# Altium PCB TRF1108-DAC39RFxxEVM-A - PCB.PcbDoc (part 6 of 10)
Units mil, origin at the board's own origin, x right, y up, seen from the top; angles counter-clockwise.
Board outline 4951.22 x 2726.56 mil, 16 copper layers (Top Layer, L2 GND1, L3 PWR1, L4 GND2, L5 PWR2, L6 GND3, L7 Ctrl Signal 1, L8 GND4, L9 GND5, L10 Ctrl Signal 2, L11 GND6, L12 PWR3, L13 GND7, L14 PWR4, L15 GND8, Bottom Layer), stack 80.2 mil thick; 705 components, 433 nets, 3633 pads, 1678 vias.
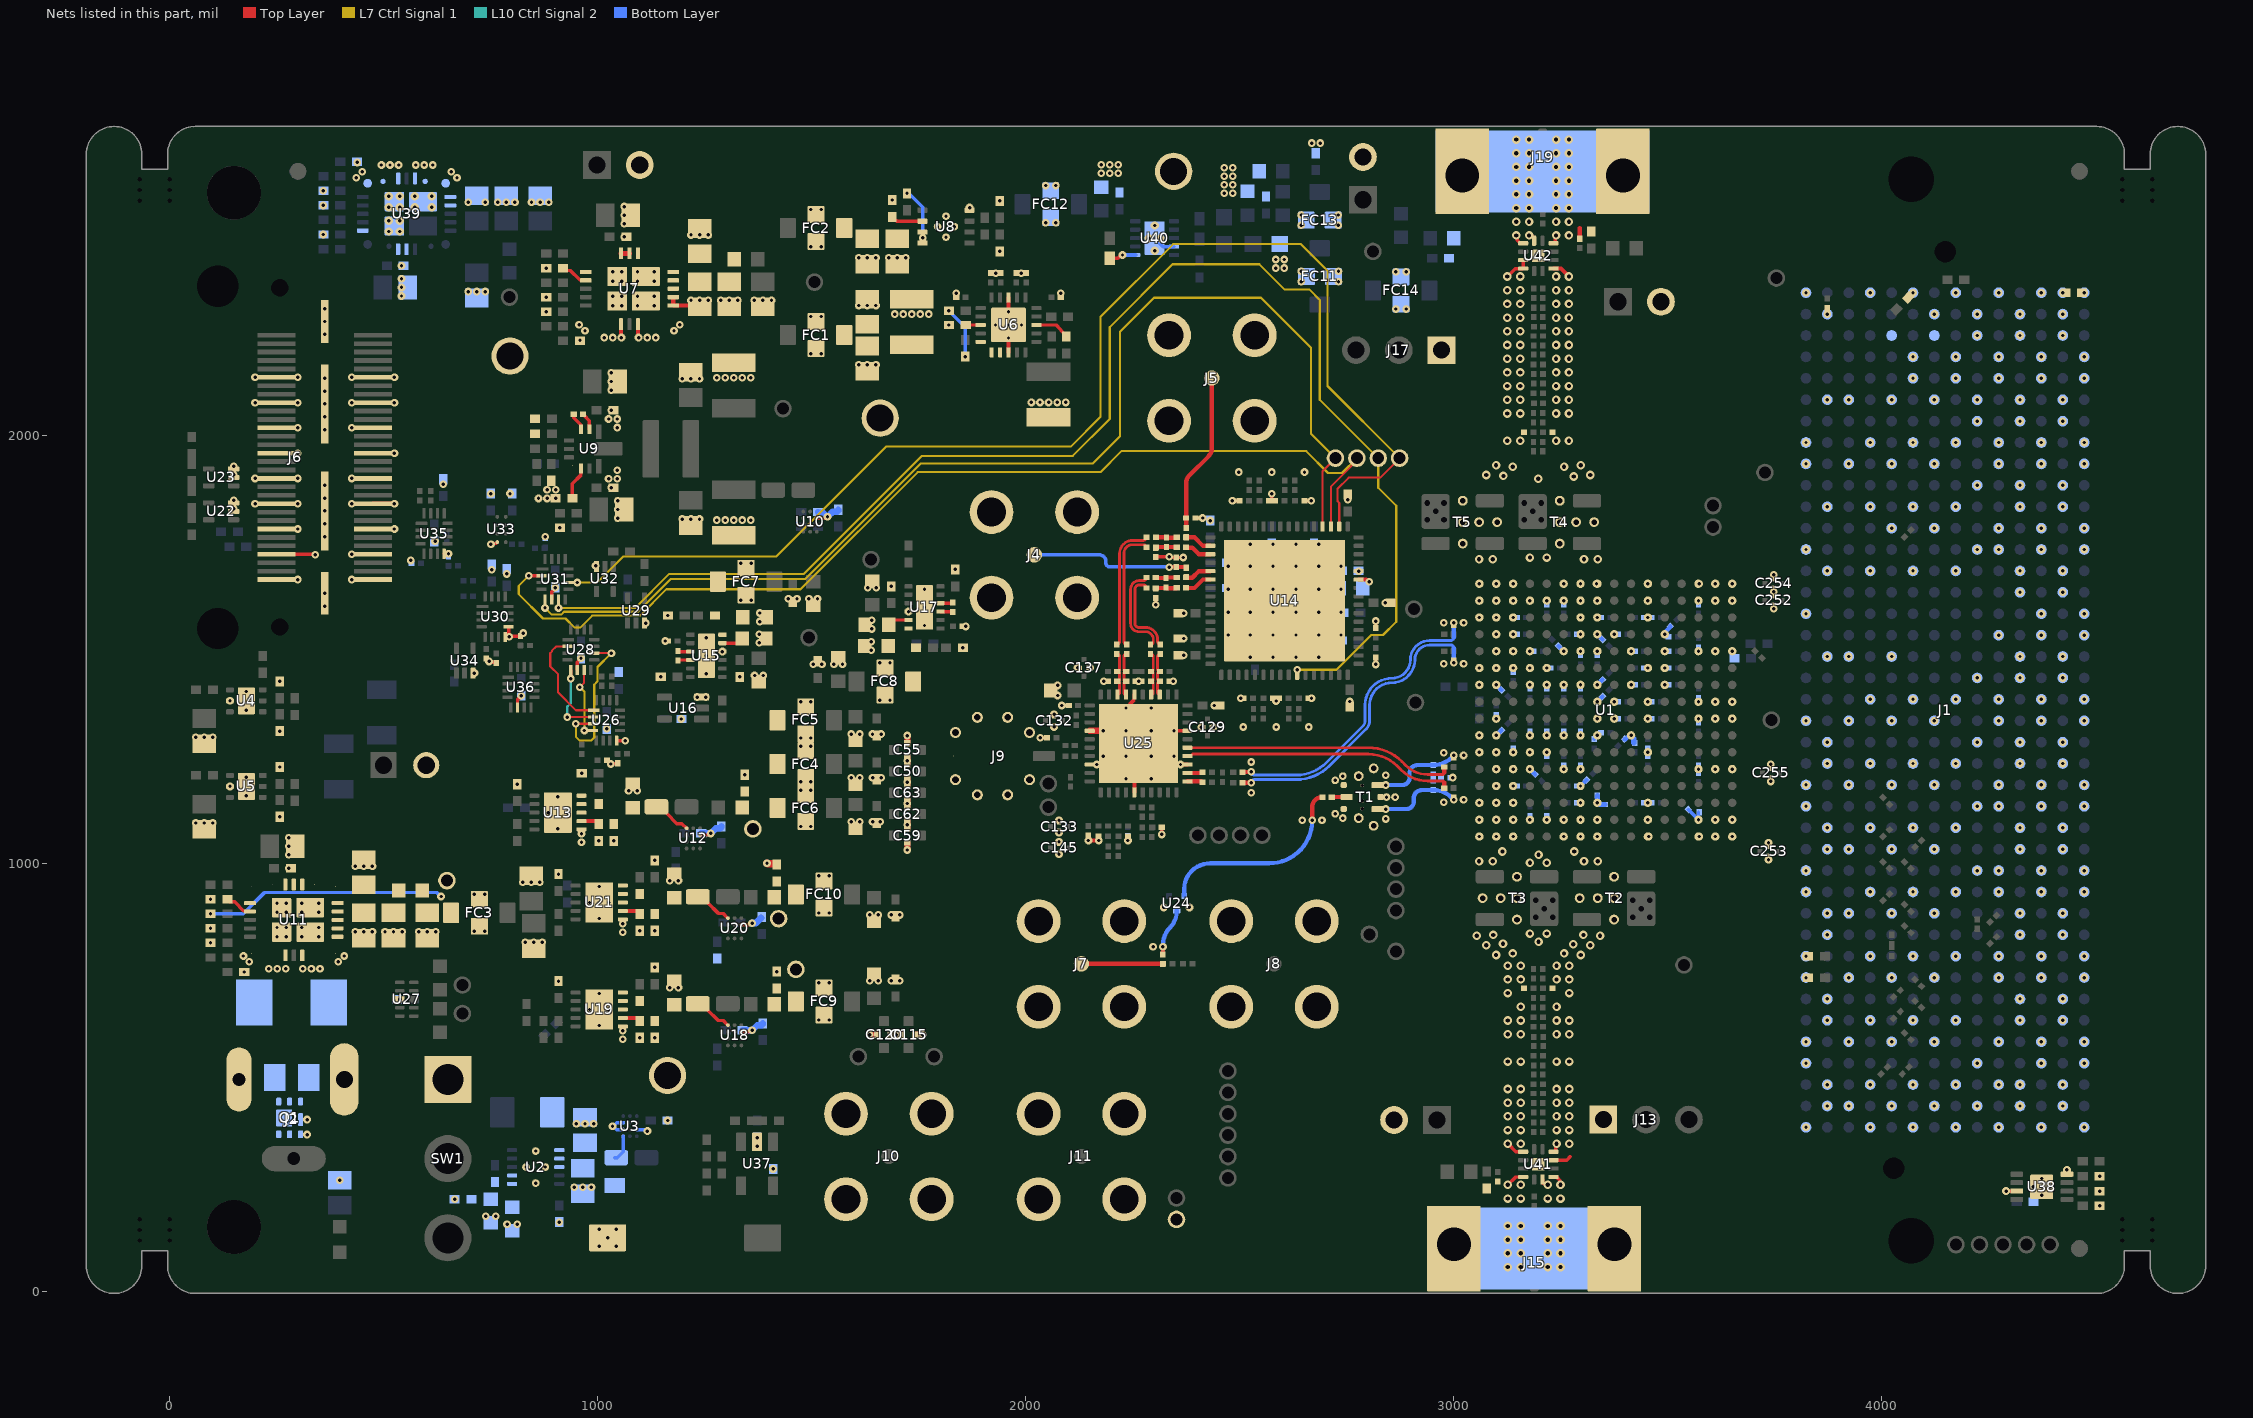
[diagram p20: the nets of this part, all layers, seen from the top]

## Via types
v1: diameter 18, hole 8, Top Layer to Bottom Layer, tented both sides, 1468 vias
v2: diameter 20, hole 10.01, Top Layer to Bottom Layer, 187 vias
v3: diameter 19.68, hole 7.87, Top Layer to Bottom Layer, tented both sides, 16 vias
v4: diameter 19.68, hole 7.87, Top Layer to Bottom Layer, 6 vias
v5: diameter 18/18/18/18/18/18/18/18/18/18/18/18/18/18/18/18 (per signal layer), hole 8, Top Layer to Bottom Layer, tented both sides, 1 vias

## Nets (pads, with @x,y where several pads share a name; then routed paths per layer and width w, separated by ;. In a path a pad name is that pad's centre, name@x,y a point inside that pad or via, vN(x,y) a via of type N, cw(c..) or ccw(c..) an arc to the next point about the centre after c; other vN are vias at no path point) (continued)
GND: C2.1 C3.1 C4.2 C5.1 C6.1 C7.1 C8.1 C9.1 C10.1 C11.1 C12.1 C13.1 C15.1 C16.1 C17.1 C18.1 C19.1 C20.1 C21.1 C22.1 C23.1 C24.1 C25.1 C26.1 C27.1 C28.1 C29.1 C30.1 C31.1 C33.1 C34.1 C35.1 C36.1 C37.2 C38.1 C39.1 C40.1 C41.1 C42.1 C43.1 C44.1 C45.1 C46.1 C47.1 C48.2 C49.1 C50.2 C51.1 C52.1 C53.1 C54.1 C55.2 C56.1 C57.1 C58.1 C59.2 C60.1 C61.1 C62.2 C63.2 C67.1 C68.1 C69.1 C70.1 C71.1 C72.1 C77.1 C78.1 C79.1 C80.1 C81.1 C82.1 C94.1 C95.1 C96.2 C97.1 C98.1 C100.1 C101.1 C102.1 C103.1 C104.1 C105.1 C106.1 C108.1 C109.1 C110.1 C111.1 C112.1 C113.2 C114.1 C115.2 C116.1 C117.1 C118.1 C119.1 C120.2 C121.1 C122.2 C123.1 C124.1 C125.1 C126.1 C127.1 C128.1 C129.2 C130.2 C132.2 C133.2 C137.2 C145.2 C146.1 C147.1 C148.2 C154.1 C158.1 C159.2 C160.1 C161.2 C162.2 C163.2 C164.1 C165.2 C166.2 C167.2 C168.2 C169.2 C170.1 C171.1 C172.1 C173.2 C174.1 C175.1 C176.1 C177.1 C178.1 C179.1 C180.1 C181.2 C182.2 C184.2 C185.2 C186.2 C187.2 C188.1 C189.2 C190.1 C191.1 C192.1 C193.1 C194.1 C195.1 C196.1 C197.1 C198.1 C199.1 C200.1 C201.1 C202.1 C203.1 C204.1 C205.1 C206.1 C207.1 C208.1 C209.1 C210.1 C211.1 C212.1 C213.2 C214.2 C215.2 C216.2 C217.2 C218.2 C219.1 C220.1 C221.1 C222.1 C223.1 C224.1 C225.1 C226.1 C227.1 C228.1 C229.1 C230.1 C231.1 C232.1 C233.1 C234.1 C235.1 C236.2 C237.2 C238.2 C239.2 C240.2 C241.2 C242.1 C243.1 C244.1 C245.1 C246.1 C247.1 C248.1 C249.1 C250.1 C251.1 C252.2 C253.2 C254.2 C255.2 C256.1 C257.1 C258.1 C259.1 C260.1 C261.1 C262.1 C263.2 C264.2 C274.2 C275.2 C276.2 D1.2 FC1.2 FC2.2 FC3.2 FC4.2 FC5.2 FC6.2 FC7.2 FC8.2 FC9.2 FC10.2 FC11.2 FC12.2 FC13.2 FC14.2 J1.A1 J1.A4 J1.A5 J1.A8 J1.A9 J1.A12 J1.A13 J1.A16 J1.A17 J1.A20 J1.A21 J1.A24 J1.A25 J1.A28 J1.A29 J1.A32 J1.A33 J1.A36 J1.A37 J1.A40 J1.B2 J1.B3 J1.B6 J1.B7 J1.B10 J1.B11 J1.B14 J1.B15 J1.B18 J1.B19 J1.B22 J1.B23 J1.B26 J1.B27 J1.B30 J1.B31 J1.B34 J1.B35 J1.B38 J1.B39 J1.C1 J1.C4 J1.C5 J1.C8 J1.C9 J1.C12 J1.C13 J1.C17 J1.C20 J1.C21 J1.C24 J1.C25 J1.C28 J1.C29 J1.C32 J1.C33 J1.C36 J1.C38 J1.C40 J1.D2 J1.D3 J1.D6 J1.D7 J1.D10 J1.D13 J1.D19 J1.D22 J1.D25 J1.D28 J1.D37 J1.D39 J1.E1 J1.E4 J1.E5 J1.E8 J1.E11 J1.E14 J1.E20 J1.E23 J1.E26 J1.E29 J1.E32 J1.E35 J1.E38 J1.E40 J1.F2 J1.F3 J1.F6 J1.F9 J1.F12 J1.F21 J1.F24 J1.F27 J1.F30 J1.F33 J1.F36 J1.F39 J1.G1 J1.G4 J1.G5 J1.G8 J1.G11 J1.G14 J1.G20 J1.G23 J1.G26 J1.G29 J1.G32 J1.G35 J1.G38 J1.G40 J1.H3 J1.H6 J1.H9 J1.H12 J1.H18 J1.H21 J1.H24 J1.H27 J1.H30 J1.H33 J1.H36 J1.H39 J1.J1 J1.J8 J1.J11 J1.J14 J1.J20 J1.J23 J1.J26 J1.J29 J1.J32 J1.J35 J1.J38 J1.J40 J1.K6 J1.K9 J1.K18 J1.K21 J1.K24 J1.K27 J1.K30 J1.K33 J1.K36 J1.K39 J1.L2 J1.L6 J1.L11 J1.L14 J1.L18 J1.L22 J1.L23 J1.L26 J1.L27 J1.L30 J1.L31 J1.L34 J1.L35 J1.L38 J1.L39 J1.M1 J1.M8 J1.M9 J1.M13 J1.M16 J1.M21 J1.M24 J1.M25 J1.M28 J1.M29 J1.M32 J1.M33 J1.M36 J1.M37 J1.M40 J1.Y1 J1.Y4 J1.Y5 J1.Y8 J1.Y9 J1.Y12 J1.Y13 J1.Y16 J1.Y17 J1.Y20 J1.Y21 J1.Y24 J1.Y25 J1.Y28 J1.Y29 J1.Y32 J1.Y33 J1.Y36 J1.Y37 J1.Y40 J1.Z2 J1.Z3 J1.Z6 J1.Z7 J1.Z10 J1.Z11 J1.Z14 J1.Z15 J1.Z18 J1.Z19 J1.Z22 J1.Z23 J1.Z26 J1.Z27 J1.Z30 J1.Z31 J1.Z34 J1.Z35 J1.Z38 J1.Z39 J3.2 J4.2 J4.3 J4.4 J4.5 J5.2 J5.3 J5.4 J5.5 J6.1 J6.2 J6.7 J6.8 J6.13 J6.14 J6.19 J6.20 J6.25 J6.26 J6.31 J6.32 J6.37 J6.38 J6.43 J6.44 J6.49 J6.50 J6.MP1 J6.MP2 J6.MP3 J6.MP4 J7.2 J7.3 J7.4 J7.5 J8.2 J8.3 J8.4 J8.5 J9.2 J10.2 J10.3 J10.4 J10.5 J11.2 J11.3 J11.4 J11.5 J12.2 J13.1 J14.2 J15.2 J15.3 J15.4 J16.2 J17.1 J18.2 J19.2 J19.3 J19.4 PP47.1 Q1.4 Q1.7 R3.1 R4.1 R5.1 R13.1 R14.1 R19.1 R21.1 R22.1 R23.1 R24.1 R26.1 R28.1 R29.1 R30.1 R33.1 R38.1 R39.1 R41.1 R42.1 R44.1 R47.1 R51.1 R52.1 R53.1 R55.1 R60.1 R61.1 R62.1 R66.1 R67.1 R71.1 R72.1 R73.1 R74.1 R75.1 R76.1 R77.1 R78.1 R79.1 R80.1 R81.1 R82.1 R83.1 R86.1 R87.1 R91.1 R92.1 R94.1 R99.1 R100.1 R101.1 R109.1 R110.1 R125.1 R126.1 R134.1 R137.1 R138.2 R139.2 R140.2 R141.2 R145.2 R147.1 R154.2 R155.2 R158.1 R162.1 R167.1 R169.1 R175.1 R180.1 R181.1 R182.1 R185.2 R192.2 R208.1 R213.1 R214.1 R215.1 R231.1 R232.1 R233.1 R234.1 R237.1 R242.2 R256.1 SW2.2 T1.1 T1.3 T1.5 T2.5 T3.5 T4.5 T5.5 TP1.1 TP2.1 TP3.1 U1.A1 U1.A2 U1.A3 U1.A6 U1.A9 U1.A10 U1.A11 U1.A14 U1.A15 U1.A16 U1.B1 U1.B2 U1.B3 U1.B6 U1.B9 U1.B10 U1.B11 U1.B12 U1.B13 U1.B14 U1.B15 U1.B16 U1.C6 U1.C9 U1.C10 U1.C14 U1.C15 U1.C16 U1.D10 U1.D14 U1.D15 U1.E1 U1.E2 U1.E3 U1.E10 U1.E11 U1.E13 U1.E14 U1.E15 U1.F6 U1.F12 U1.F13 U1.F14 U1.F15 U1.F16 U1.G7 U1.G9 U1.G10 U1.G11 U1.G12 U1.G13 U1.G15 U1.G16 U1.H1 U1.H2 U1.H3 U1.H6 U1.H8 U1.H9 U1.H15 U1.J1 U1.J2 U1.J3 U1.J6 U1.J8 U1.J9 U1.K5 U1.K7 U1.K9 U1.K10 U1.K11 U1.K12 U1.K13 U1.K15 U1.K16 U1.L5 U1.L6 U1.L12 U1.L13 U1.L14 U1.L15 U1.L16 U1.M1 U1.M2 U1.M3 U1.M5 U1.M7 U1.M9 U1.M10 U1.M11 U1.M13 U1.M14 U1.M15 U1.N5 U1.N8 U1.N9 U1.N10 U1.N14 U1.N15 U1.P6 U1.P9 U1.P10 U1.P14 U1.P15 U1.P16 U1.R1 U1.R2 U1.R3 U1.R6 U1.R9 U1.R10 U1.R11 U1.R12 U1.R13 U1.R14 U1.R15 U1.R16 U1.T1 U1.T2 U1.T3 U1.T6 U1.T9 U1.T10 U1.T11 U1.T14 U1.T15 U1.T16 U2.11 U3.B3 U3.C1 U3.C3 U4.5 U4.7@179.22,1357.95 U4.7@179.22,1379.61 U4.7@179.22,1401.26 U5.5 U5.7@179.22,1157.95 U5.7@179.22,1179.61 U5.7@179.22,1201.26 U6.8 U6.18 U6.21 U7.1 U7.2 U7.3 U7.5 U7.6 U7.7 U7.8 U7.9 U7.16 U7.17 U7.20 U7.25 U7.26 U7.28 U8.4 U8.9 U9.5 U9.9 U9.11 U10.C1 U11.1 U11.2 U11.3 U11.5 U11.6 U11.7 U11.8 U11.9 U11.16 U11.17 U11.20 U11.25 U11.26 U11.28 U12.C1 U13.6 U13.11 U14.65 U15.4 U15.13 U16.3 U17.4 U17.13 U18.C1 U19.6 U19.11 U20.C1 U21.6 U21.11 U22.2 U22.3 U23.2 U23.3 U24.GND U25.5 U25.13 U25.17 U25.26 U25.34 U25.38 U25.41 U26.8 U27.3@537.69,682.33 U28.6 U29.3 U30.8 U30.9 U31.6 U32.3 U33.D1 U34.3 U35.8 U36.6 U37.2 U38.4 U38.7 U38.9 U39.1 U39.2 U39.3 U39.5 U39.6 U39.7 U39.8 U39.9 U39.16 U39.17 U39.20 U39.25 U39.26 U39.28 U40.4 U40.6 U40.11@2301.04,2460.58 U41.1 U41.3 U41.4 U41.7 U41.10 U41.12 U41.13 U42.1 U42.3 U42.4 U42.7 U42.10 U42.12 U42.13 | length 4622.8
  Top Layer w8: v1(199.41,1840.04) J6.20@249.41,1840.04 v1(299.41,1840.04) ; v1(199.41,1899.09) J6.26@249.41,1899.09 v1(299.41,1899.09) ; v1(199.41,2076.26) J6.44@249.41,2076.26 v1(299.41,2076.26) ; v1(199.41,2135.31) J6.50@249.41,2135.31 v1(299.41,2135.31) ; J6.2@249.41,1662.87 v1(299.41,1662.87) ; J6.8@249.41,1721.93 339.1,1721.93 v1(339.85,1721.18) ; J6.14@249.41,1780.98 v1(299.41,1780.98) ; J6.32@249.41,1958.15 v1(299.41,1958.15) ; J6.38@249.41,2017.2 v1(299.41,2017.2) ; v1(425,1662.87) J6.1@475,1662.87 ; v1(425,1721.93) J6.7@475,1721.93 ; v1(425,1840.04) J6.19@475,1840.04 ; v1(425,1899.09) J6.25@475,1899.09 ; v1(425,2017.2) J6.37@475,2017.2 ; v1(425,2076.26) J6.43@475,2076.26 v1(525,2076.26) ; v1(425,2135.31) J6.49@475,2135.31 v1(525,2135.31) ; J6.13@475,1780.98 v1(525,1780.98) ; J6.31@475,1958.15 v1(525,1958.15) ; U35.8@641.32,1723.18 v1(651.32,1723.18) ; v1(746.12,1471.54) 748.04,1469.63 760.82,1469.63 R155.2@762.82,1467.63 ; v1(750.54,1745.15) 752.45,1747.07 762.17,1747.07 765.26,1750.15 U33.D1@765.54,1750.15 ; U30.9@791.94,1552.67 791.94,1530.11 v1(793,1529.05) 794.73,1530.77 R158.1@819.67,1530.77 ; U36.6@812.57,1364.05 812.57,1381.92 821,1390.35 v1(821,1391.61) ; U31.6@892.57,1616.55 892.57,1634.42 901,1642.85 v1(901,1644.11) ; U28.6@952.57,1451.55 952.57,1469.42 961,1477.85 v1(961,1479.11) ; R145.2@1021.21,1241.1 1022,1241.1 1030.34,1232.75 v1(1030.34,1232.05) 1031.16,1232.86 1045.6,1232.86 R147.1@1046.42,1233.68 ; U26.8@1044.07,1286.55 v1(1064.07,1286.55) ; U12.C1@1239.08,1066.1 1257.74,1066.1 1261.37,1069.73 v1(1264.08,1069.73) ; U18.C1@1335.57,606.1 v1@1354.24,606.1 ; U20.C1@1335.57,856.1 1354.24,856.1 1357.87,859.73 v1(1360.57,859.73) ; U10.C1@1511.85,1806.05 1530.52,1806.05 1534.14,1809.68 v1(1536.85,1809.68) ; R19.1@1837.66,2322.05 v1(1837.66,2332.05) ; R21.1@1918.3,2378.7 R22.1@1941.99,2378.7 ; R23.1@1977.36,2378.7 R24.1@2001.04,2378.7 ; v1(2034.02,1293.15) R126.1@2050.32,1293.15 ; R26.1@2081.68,2322.05 v1(2081.68,2332.05) ; v1(2084.07,1368.57) C148.2@2100.37,1368.57 ; U25.38@2149.41,1230.78 v1(2165.71,1230.78) 2214.37,1230.78 U25.41@2234.06,1250.46 2253.74,1230.78 U25.41@2253.74,1192.12 ; C188.1@2196.23,2413.33 2215.42,2413.33 2223.3,2421.21 v1(2225.93,2421.21) ; U25.41@2234.06,1362.67 2252.82,1381.43 2252.82,1393.24 U25.26@2253.74,1394.17 ; v1(2303.69,1603.99) R66.1@2303.69,1620.28 ; R71.1@2303.79,1715.13 2304.46,1715.8 2334.81,1715.8 v1(2335.48,1716.48) ; v1(2317.63,1067.47) R125.1@2317.63,1083.77 ; U25.41@2318.99,1291.1 U25.41@2330.51,1302.62 ; v1@2335.48,1714.48 R62.1@2351.78,1714.48 v1(2368.08,1714.48) ; U25.41@2346.26,1309.52 U25.17@2377.76,1309.52 ; R67.1@2396.78,1806.69 v1(2413.08,1806.69) ; v1(2482.76,1846.92) R81.1@2499.06,1846.92 ; v1(2502.05,1385.46) R74.1@2509.14,1385.46 ; 2575,1846.92 v1(2575,1863.22) ; R75.1@2577.76,1385.46 R76.1@2584.85,1385.46 ; v1(2584.85,1379.17) R76.1@2584.85,1385.46 ; R76.1@2591.93,1385.46 R76.1@2584.85,1385.46 ; R78.1@2650.94,1846.92 v1(2667.24,1846.92) ; R77.1@2660.55,1385.46 v1(2667.64,1385.46) ; v1(2817.76,1464.58) R72.1@2817.76,1480.88 ; R73.1@2817.76,1549.66 v1(2817.76,1565.96) ; v2@3126,248 3126,248.54 v2(3126.18,248.72) 3144.49,267.03 U41.10@3162.17,267.03 ; v2@3127,343 3127.91,343 3144.82,326.09 U41.7@3162.17,326.09 ; v2@3128,249 v2@3130.02,251.02 ; v2@3128,2374 3128.33,2374 3143.82,2389.49 U42.4@3160,2389.49 ; v2@3147,2464 3148.16,2462.84 3148.16,2455.66 3155.28,2448.54 U42.1@3162.17,2448.54 ; U42.4@3160,2389 3160.76,2389 3162.17,2390.41 U42.3@3162.17,2409.17 ; v2@3178,2469 3178,2467.97 3181.41,2464.56 3184.54,2464.56 3187.76,2461.34 U42.12@3187.76,2454.45 ; U41.12@3207.44,261.13 3207.44,254.24 3210.66,251.02 3216.98,251.02 v2@3219,249 ; U41.1@3233.03,267.03 3239.92,267.03 3247.04,259.92 3247.04,249.96 v2@3249,248 ; U41.3@3233.03,306.4 3263.4,306.4 3272,315 ; U41.4@3233.03,326.09 3236.8,326.09 3237.73,327.01 3237.73,340.73 v2@3241,344 ; U42.10@3233.03,2448.54 3235.8,2448.54 3236.72,2449.46 3236.72,2464.72 v2@3240,2468 ; v1@3735.31,1008.04 C253.2@3735.31,1018.04 ; C253.2@3735.31,1037.73 v1(3735.31,1047.89) ; v1@3740.61,1191.1 C255.2@3740.61,1201.1 ; C255.2@3740.61,1220.78 v1@3740.61,1230.78 ; v1@3747.18,1594.53 C252.2@3747.18,1604.53 ; C252.2@3747.18,1624.22 C254.2@3747.18,1644.22 ; C254.2@3747.18,1663.9 v1@3747.18,1673.9 ; v1(3872.81,2283.06) R231.1@3872.81,2297.03 ; R208.1@4061.7,2321.94 v1(4072.81,2333.06) ; v1(4290.24,234.2) U38.7@4315.24,234.2 ; U38.4@4432.49,273.57 v1(4432.49,283.57)
  Top Layer w9: U6.18@1959.67,2193.7 U6.21@1959.67,2227.17 ; U6.21@1959.67,2288.19 U6.8@1959.67,2321.65 ; U25.5@2253.74,1165.82 U25.41@2253.74,1191.97
  Top Layer w10: U7.3@1054.5,2259.65 1054.58,2259.57 1054.58,2229.03 v1(1055.36,2228.25) ; U7.5@1093.87,2259.65 1093.87,2229.74 v1(1095.36,2228.25) ; U7.9@1176.55,2322.64 U7.8@1176.55,2302.95 1216.33,2302.95 1217.89,2304.51 v1(1217.89,2315) ; C158.1@2146.4,1063.18 v1(2146.4,1053.18) v1(2170.4,1053.18) R134.1@2170.4,1063.18 ; v1(2182.33,1425.17) R138.2@2192.33,1425.17 ; v1(2238.67,1053.18) R137.1@2238.67,1063.18 ; v1(2263.59,1425.17) R140.2@2271.07,1425.17 ; U25.41@2293.11,1250.46 2312.8,1230.78 U25.13@2377.76,1230.78 ; R141.2@2334.85,1425.17 v1(2344.85,1425.17) ; U42.7@3233.03,2389.49 3250.38,2389.49 3268,2371.87 v2@3268,2371 ; 3294,2484 3294.45,2483.55 C276.2@3294.45,2459.08
  Top Layer w11: J6.19@475,1840.04 v1(525,1840.04)
  Top Layer w12: U7.17@1054.5,2425 U7.16@1074.19,2425
  Top Layer w14: v1(1635.23,599.69) C120.2@1653.1,599.69 ; C120.2@1684.61,599.68 C115.2@1710.3,599.69 ; v1(1723.36,1031.1) C59.2@1723.36,1048.97 ; C59.2@1723.37,1080.48 C62.2@1723.36,1098.97 ; C62.2@1723.37,1130.48 C63.2@1723.36,1148.97 ; C63.2@1723.37,1180.48 C50.2@1723.36,1198.97 ; C50.2@1723.37,1230.48 C55.2@1723.36,1248.97 ; C55.2@1723.37,1280.48 v1(1723.37,1298.35) ; C115.2@1741.8,599.68 v1(1759.68,599.68)
  Top Layer w15: U25.34@2149.41,1309.52 U25.41@2180.91,1309.52
  Top Layer w18: v1(1395.55,1000.42) 1396.95,999.02 1417.76,999.02 1418.61,998.18 C125.1@1418.61,996.84
  Bottom Layer w5: v1(3099.18,1338.1) C173.2@3099.18,1346.76 ; v1(3138.55,1180.62) C238.2@3147.21,1180.62 ; v1(3138.55,1259.36) C248.1@3138.55,1268.02 ; C251.1@3138.55,1447.55 v1(3138.55,1456.21) ; v1(3138.55,1534.95) C214.2@3147.21,1534.95 ; v1(3138.55,1574.32) C213.2@3147.21,1574.32 ; v1(3177.92,1101.88) C236.2@3177.92,1110.54 ; v1(3177.92,1298.73) C226.1@3177.92,1307.39 ; C247.1@3177.92,1408.18 v1(3177.92,1416.84) ; v1(3177.92,1495.58) C224.1@3186.58,1495.58 ; v1(3217.29,1101.88) C239.2@3217.29,1110.54 ; v1(3217.29,1298.73) C225.1@3217.29,1307.39 ; C246.1@3217.29,1408.18 v1(3217.29,1416.84) ; v1(3217.29,1456.21) C223.1@3225.95,1456.21 ; C218.2@3217.29,1605.03 v1(3217.29,1613.69) ; v1(3256.66,1219.99) C220.1@3256.66,1228.65 ; v1(3256.66,1298.73) C221.1@3256.66,1307.39 ; C222.1@3256.66,1408.18 v1(3256.66,1416.84) ; C217.2@3256.66,1605.03 v1(3256.66,1613.69) ; C240.2@3287.37,1141.25 v1(3296.03,1141.25) ; C241.2@3287.37,1180.62 v1(3296.03,1180.62) ; C216.2@3287.37,1534.95 v1(3296.03,1534.95) ; v1(3296.03,1219.99) C242.1@3296.03,1228.65 ; v1(3296.03,1298.73) C243.1@3296.03,1307.39 ; C244.1@3296.03,1408.18 v1(3296.03,1416.84) ; C245.1@3296.03,1486.92 v1(3296.03,1495.58) ; C196.1@3335.4,1486.92 v1(3335.4,1495.58) ; v1(3335.4,1574.32) C235.1@3344.06,1574.32 ; v1(3374.77,1338.1) C228.1@3383.43,1338.1 ; v1(3374.77,1377.47) C194.1@3383.43,1377.47 ; v1(3374.77,1534.95) C232.1@3383.43,1534.95 ; v1(3414.14,1416.84) C203.1@3422.8,1416.84 ; v1(3414.14,1495.58) C195.1@3422.8,1495.58 ; C210.1@3444.85,1141.25 C208.1@3462.17,1141.25 ; C230.1@3444.85,1456.21 v1(3453.51,1456.21) ; C199.1@3444.85,1574.32 C234.1@3462.17,1574.32 ; R175.1@3453.51,1250.7 C193.1@3453.51,1268.02 ; v1(3453.51,1338.1) C229.1@3462.17,1338.1 ; v1(3453.51,1377.47) C202.1@3462.17,1377.47 ; v1(3492.88,1416.84) C259.1@3501.54,1416.84 ; v1(3492.88,1456.21) C260.1@3501.54,1456.21 ; v1(3492.88,1495.58) C258.1@3501.54,1495.58 ; v1(3492.88,1534.95) C261.1@3501.54,1534.95 ; C212.1@3571.62,1211.33 C207.1@3571.62,1228.65 ; C206.1@3571.62,1329.44 v1(3571.62,1338.1) ; v1(3571.62,1377.47) C209.1@3571.62,1386.13 ; v1(3571.62,1495.58) C197.1@3571.62,1504.24 ; C233.1@3571.62,1605.03 v1(3571.62,1613.69)
  Bottom Layer w8: v1(525,1840.04) v1@526.12,1838.92 ; v1(1034.59,385.85) v1@1036.4,385.85 ; U3.C3@1059.59,377.97 1044.28,377.97 v1@1036.4,385.85 ; U3.B3@1059.59,393.72 1044.28,393.72 v1@1036.4,385.85 ; U3.C1@1091.09,377.97 1109.75,377.97 1113.38,374.35 v1(1116.09,374.35) ; U40.11@2301.04,2460.58 2301.04,2460.51 2320.67,2440.89 U40.4@2346.32,2440.89 ; C200.1@3328.4,1290.07 3328.4,1290.86 3335.4,1297.86 v1(3335.4,1298.73) ; C191.1@3547.84,1125.66 3570.09,1103.41 v1(3571.62,1101.88) C211.1@3571.62,1119.2
  Bottom Layer w10: v1(2225.93,2421.21) U40.6@2255.77,2421.21 ; v1(3099.18,1298.73) C249.1@3111.07,1310.62 ; v1(3099.18,1416.84) C250.1@3111.07,1404.95 ; v1(3177.92,1219.99) C237.2@3189.81,1208.1 ; v1@3217.29,1257.79 v1(3217.29,1259.36) ; C215.2@3244.77,1507.47 v1(3256.66,1495.58) ; v1(3296.03,1180.62) C257.1@3309.92,1194.51 ; v1(3335.4,1377.47) C204.1@3347.29,1389.36 ; v1(3335.4,1416.84) C231.1@3347.29,1428.73 ; v1(3335.4,1534.95) C205.1@3347.29,1523.06 ; C227.1@3399.36,1289.95 3401.19,1289.95 3408.44,1297.2 v1@3412.61,1297.2 ; v1(3492.88,1534.95) 3494.41,1536.48 3494.41,1540.94 3505.66,1552.19 C198.1@3505.66,1553.73 ; v1@3570.09,1103.41 v1(3571.62,1101.88)
  Bottom Layer w12: C256.1@3335.4,1158.58 v1(3335.4,1141.25) 3337.02,1141.25 3340.72,1137.55 3352.42,1137.55 C190.1@3352.72,1137.25 ; v1(3414.14,1298.73) 3414.14,1297.11 3420.44,1290.81 3420.44,1281.71 C192.1@3420.74,1281.41
  Bottom Layer w15: R55.1@1241.95,1069.73 v1(1264.08,1069.73) 1276.13,1081.79 1286.73,1081.79 1289.08,1084.13 C48.2@1289.08,1086.1 ; v1@1361.15,610.3 1372.63,621.79 1383.23,621.79 1385.57,624.13 C113.2@1385.57,626.1 ; R38.1@1514.72,1820.68 1516.57,1818.84 1527.15,1818.84 1536.31,1809.68 v1(1536.85,1809.68) 1537.48,1809.68 1549.54,1821.74 1559.51,1821.74 1561.85,1824.08 C37.2@1561.85,1826.05
  Bottom Layer w16: R94.1@1338.45,609.73 v1(1360.57,609.73) ; v1(1360.57,859.73) 1360.96,860.11 1369.59,860.11 C122.2@1381.76,872.29
  Bottom Layer w18: U25.41@2180.91,1309.52 2180.91,1297.71 2185.97,1292.65 2185.97,1290.68 2186.81,1289.83 2188.78,1289.83 ; 2273.43,1354.8 2273.43,1356.76 2274.27,1357.61 2288.05,1357.61 U25.41@2293.11,1362.67 ; 2338.39,1289.83 2340.36,1289.83 2341.2,1290.68 2341.2,1304.46 U25.41@2346.26,1309.52
  other v1: 1003.23,104.96 1043.23,104.96 1023.23,124.96 1003.23,144.96 1043.23,144.96 788.27,156.85 811.73,156.85 910.24,161.58 738.27,175.63 761.73,175.63 4508.86,199.51 665.75,215 4508.86,234.2 945.24,243.45 965.24,243.45 985.24,243.45 397.23,259.69 4508.86,268.88 1409.63,285.96 1372.23,338.96 1372.23,358.96 320.91,366.3 3822.81,383.06 3972.81,383.06 4072.81,383.06 4172.81,383.06 4272.81,383.06 4372.81,383.06 4472.81,383.06 950.24,391.56 970.24,391.56 990.24,391.56 1163.13,399.15 320.91,401.3 3872.81,433.06 3922.81,433.06 4022.81,433.06 4122.81,433.06 4222.81,433.06 4322.81,433.06 4422.81,433.06 3872.81,483.06 3972.81,483.06 4072.81,483.06 4172.81,483.06 4272.81,483.06 4322.81,483.06 4422.81,483.06 3822.81,533.06 4222.81,533.06 4372.81,533.06 4472.81,533.06 3822.81,583.06 3922.81,583.06 4022.81,583.06 4122.81,583.06 4272.81,583.06 4372.81,583.06 4472.81,583.06 1058.61,589.09 1098.61,592.32 1133.61,592.32 1697.45,599.68 1058.61,609.09 3872.81,633.06 3972.81,633.06 4072.81,633.06 4172.81,633.06 4322.81,633.06 4422.81,633.06 537.69,682.33 3872.81,683.06 4322.81,683.06 4422.81,683.06 1168.61,709.61 1188.61,709.61 908.37,724.61 1635.65,725.35 1655.65,725.35 1685.65,725.35 1705.65,725.35 3822.81,733.06 3922.81,733.06 4022.81,733.06 4122.81,733.06 4272.81,733.06 4372.81,733.06 4472.81,733.06 174.14,745.98 1418.61,746.84 231.12,753.6 251.12,753.6 271.12,753.6 311.12,753.6 331.12,753.6 351.12,753.6 1133.61,756.89 185.95,769.65 393.94,769.65 172.23,783.36 407.66,783.36 3822.81,783.06 3972.81,783.06 4072.81,783.06 4172.81,783.06 4272.81,783.06 4372.81,783.06 4472.81,783.06 2297.45,805.05 95.4,813.98 830.64,815.35 850.64,815.35 870.64,815.35 3872.81,833.06 4322.81,833.06 4422.81,833.06 1058.61,839.09 433.65,840.35 453.65,840.35 473.65,840.35 502.96,840.35 522.96,840.35 542.96,840.35 581.7,840.35 601.7,840.35 621.7,840.35 1098.61,842.32 1133.61,842.32 95.4,847.98 1058.61,859.09 1635.65,879.37 1655.65,879.37 1685.65,879.37 1705.65,879.37 3872.81,883.06 3922.81,883.06 4022.81,883.06 4122.81,883.06 4322.81,883.06 4422.81,883.06 2322.56,896.94 2382.6,896.94 95.4,915.98 3822.81,933.06 3972.81,933.06 4072.81,933.06 4172.81,933.06 4272.81,933.06 4372.81,933.06 4472.81,933.06 824.64,955.46 844.64,955.46 864.64,955.46 1168.61,959.61 1188.61,959.61 908.37,974.61 3822.81,983.06 4222.81,983.06 4272.81,983.06 4372.81,983.06 4472.81,983.06 278.06,988.68 433.65,993.42 453.65,993.42 473.65,993.42 1133.61,1006.89 3735.31,1008.2 277.9,1019.68 2077.72,1021.06 3872.81,1033.06 3922.81,1033.06 4022.81,1033.06 4122.81,1033.06 4322.81,1033.06 4422.81,1033.06 277.9,1039.68 962.11,1049.09 2077.72,1050.59 1002.11,1052.32 1037.11,1052.32 277.9,1059.68 3059.81,1062.51 3099.18,1062.51 3138.55,1062.51 3256.66,1062.51 3296.03,1062.51 3335.4,1062.51 3455.51,1062.51 3573.62,1062.51 3610.99,1062.51 3650.36,1062.51 962.11,1069.09 2077.72,1071.06 3872.81,1083.06 3972.81,1083.06 4072.81,1083.06 4172.81,1083.06 4322.81,1083.06 4422.81,1083.06 1723.37,1089.72 60.83,1094.21 80.83,1094.21 100.83,1094.21 1592.02,1097.24 1612.02,1097.24 1642.03,1097.24 1660.03,1097.24 2077.72,1100.59 2646.08,1100.59 2692.08,1100.59 3059.81,1101.88 3099.18,1101.88 3138.55,1101.88 3256.66,1101.88 3296.03,1101.88 3335.4,1101.88 3453.51,1101.88 3610.99,1101.88 3650.36,1101.88 2840.8,1103.69 257.6,1108.74 3822.81,1133.06 4222.81,1133.06 4272.81,1133.06 4372.81,1133.06 4472.81,1133.06 1723.37,1139.72 3059.81,1141.25 3099.18,1141.25 3138.55,1141.25 3453.51,1141.25 2976.81,1142.58 3022.81,1148.58 2526.85,1164.96 1072.11,1169.61 1092.11,1169.61 140.83,1179.61 3099.18,1180.62 3822.81,1183.06 3922.81,1183.06 4022.81,1183.06 4122.81,1183.06 4272.81,1183.06 4372.81,1183.06 4472.81,1183.06 811.87,1184.61 1723.37,1189.72 3740.61,1191.26 1592.02,1199.61 1612.02,1199.61 1642.03,1199.61 1662.03,1199.61 2997.43,1200.31 2840.8,1205.69 1343.13,1206.84 962.74,1210.55 3099.18,1219.99 3138.55,1219.99 3571.62,1219.99 3610.99,1219.99 3650.36,1219.99 257.6,1224.88 2361.46,1230.78 3740.61,1230.94 3872.81,1233.06 3972.81,1233.06 4072.81,1233.06 4172.81,1233.06 4322.81,1233.06 4422.81,1233.06 2526.85,1236.64 1723.37,1239.72 3022.81,1252.04 2976.81,1258.04 3059.81,1259.36 3099.18,1259.36 3177.92,1259.36 3453.51,1259.36 3872.81,1283.06 4222.81,1283.06 4322.81,1283.06 4422.81,1283.06 60.83,1294.21 80.83,1294.21 100.83,1294.21 3059.81,1298.73 1592.02,1301.97 1612.02,1301.97 1642.02,1301.97 1662.02,1301.97 257.6,1308.74 1021,1314.11 2409.81,1317.7 2439.33,1317.7 2066.19,1318.42 2507.97,1318.42 2585.1,1318.42 2661.22,1318.42 3822.81,1333.06 3922.81,1333.06 4022.81,1333.06 4122.81,1333.06 4272.81,1333.06 4372.81,1333.06 4472.81,1333.06 1195.34,1337.1 3335.4,1338.1 3610.99,1338.1 3650.36,1338.1 2066.19,1347.95 2440.32,1368.57 3610.99,1377.47 3650.36,1377.47 2757.09,1377.91 140.83,1379.61 3972.81,1383.06 4072.81,1383.06 4172.81,1383.06 4272.81,1383.06 4372.81,1383.06 4472.81,1383.06 1232.59,1388.28 1252.59,1388.28 2074.38,1392.07 2074.38,1415.54 3059.81,1416.84 257.6,1424.88 4222.81,1433.06 4322.81,1433.06 4422.81,1433.06 1147.19,1435.51 1331.37,1435.51 1366.37,1438.7 1386.37,1438.7 711.95,1444.4 2121.03,1456.7 2150.56,1456.7 3059.81,1456.21 3099.18,1456.21 3177.92,1456.21 1503.86,1464.86 1523.86,1464.86 1551.86,1464.86 1571.86,1464.86 2976.81,1466.45 3022.81,1466.45 3872.81,1483.06 3922.81,1483.06 4022.81,1483.06 4322.81,1483.06 4422.81,1483.06 2368.74,1485.74 1291.37,1494.57 3099.18,1495.58 3138.55,1495.58 3610.99,1495.58 3650.36,1495.58 1638.98,1497.85 1852.44,1503.68 1377.39,1515.08 1638.98,1517.85 1157.43,1519.25 2368.74,1525.11 4272.81,1533.06 4372.81,1533.06 4472.81,1533.06 1377.39,1535.08 3099.18,1534.95 825.97,1537.86 1639.96,1547.54 1859.53,1553.37 1112.21,1561.21 2976.81,1562 3022.81,1562 1378.37,1564.77 1639.96,1567.54 3059.81,1574.32 3099.18,1574.32 3296.03,1574.32 3453.51,1574.32 1163.91,1578.94 3822.81,1583.06 4372.81,1583.06 4472.81,1583.06 1378.37,1584.77 2368.74,1584.17 1725.98,1588.05 3747.18,1594.37 362.2,1600.79 2840.32,1608.22 3059.81,1613.69 3099.18,1613.69 3138.55,1613.69 3177.92,1613.69 3296.03,1613.69 3335.4,1613.69 3453.51,1613.69 3610.99,1613.69 3650.36,1613.69 1445.49,1617.76 1465.49,1617.76 1493.49,1617.76 1513.49,1617.76 362.2,1630.79 4322.81,1633.06 4422.81,1633.06 3747.18,1634.06 1630.98,1643.92 1650.98,1643.92 1685.98,1647.11 3059.81,1653.06 3099.18,1653.06 3138.55,1653.06 3256.66,1653.06 3296.03,1653.06 3333.4,1653.06 3453.51,1653.06 3573.62,1653.06 3610.99,1653.06 3650.36,1653.06 3747.18,1673.74 787.57,1676.1 3872.81,1683.06 3972.81,1683.06 4072.81,1683.06 4172.81,1683.06 4322.81,1683.06 4422.81,1683.06 752.57,1686.1 1834.79,1686.48 995,1695 563.12,1707.57 3822.81,1733.06 4222.81,1733.06 4272.81,1733.06 4372.81,1733.06 4472.81,1733.06 620.06,1752.36 362.2,1763.31 877.57,1763.08 911.59,1783.43 4022.81,1783.06 4122.81,1783.06 4272.81,1783.06 4372.81,1783.06 4472.81,1783.06 362.2,1793.31 2431.3,1800.7 1277.75,1801.89 1297.75,1801.89 1317.75,1801.89 1337.75,1801.89 1357.75,1801.89 1197.75,1804.13 1217.75,1804.13 1237.75,1804.13 1046.44,1806.54 362.2,1823.31 1046.44,1826.54 149.41,1828.15 3872.81,1833.06 3972.81,1833.06 4072.81,1833.06 4172.81,1833.06 4322.81,1833.06 4422.81,1833.06 1046.44,1846.54 149.41,1847.83 2752.17,1849.48 861.59,1852.43 881.59,1852.43 901.59,1852.43 362.2,1853.31 750.54,1863.58 795.02,1863.78 881.59,1872.43 901.59,1872.43 1031.74,1877.84 362.2,1883.31 4222.81,1883.06 4322.81,1883.06 4422.81,1883.06 639.08,1885.39 1025.36,1898.37 1045.36,1898.37 149.41,1907.52 2497.9,1913.97 2575.02,1913.97 2651.15,1913.97 1045.36,1918.37 149.41,1927.2 3822.81,1933.06 3922.81,1933.06 4022.81,1933.06 4122.81,1933.06 4272.81,1933.06 4372.81,1933.06 4472.81,1933.06 3822.81,1983.06 3972.81,1983.06 4072.81,1983.06 4172.81,1983.06 4272.81,1983.06 4372.81,1983.06 4472.81,1983.06 362.2,2013.31 1045.36,2018.01 4222.81,2033.06 4322.81,2033.06 4422.81,2033.06 1025.36,2038.01 1045.36,2038.01 362.2,2043.31 1031.74,2058.54 362.2,2073.31 2013.29,2076.7 2033.29,2076.7 2053.29,2076.7 2073.29,2076.7 2093.29,2076.7 3872.81,2083.06 3922.81,2083.06 4022.81,2083.06 4122.81,2083.06 4222.81,2083.06 4322.81,2083.06 4422.81,2083.06 362.2,2103.31 1031.59,2105.59 1031.59,2125.59 1197.75,2132.24 1217.75,2132.24 1237.75,2132.24 362.2,2133.31 4072.81,2133.06 4172.81,2133.06 4272.81,2133.06 4372.81,2133.06 4472.81,2133.06 1277.75,2134.49 1297.75,2134.49 1317.75,2134.49 1337.75,2134.49 1357.75,2134.49 1031.59,2145.59 1609.88,2164.5 1629.88,2164.5 1649.88,2164.5 4072.81,2183.06 4172.81,2183.06 4272.81,2183.06 4372.81,2183.06 4472.81,2183.06 958.62,2222.16 1015.36,2228.25 1035.36,2228.25 1115.36,2228.25 1135.36,2228.25 4222.81,2233.06 4322.81,2233.06 4422.81,2233.06 362.2,2235.83 970.19,2244.29 1178.18,2244.29 1820.34,2257.68 956.47,2258.01 1191.9,2258.01 362.2,2265.83 1693.62,2283.11 1713.62,2283.11 1733.62,2283.11 1753.62,2283.11 1773.62,2283.11 4122.81,2283.06 4222.81,2283.06 4322.81,2283.06 4422.81,2283.06 879.64,2288.63 362.2,2295.83 1609.88,2303.11 1629.88,2303.11 1649.88,2303.11 1237.89,2315 1257.89,2315 1287.2,2315 1307.2,2315 1327.2,2315 1365.94,2315 1385.94,2315 1405.94,2315 879.64,2322.63 541.49,2325.3 3822.81,2333.06 3972.81,2333.06 4172.81,2333.06 4272.81,2333.06 4372.81,2333.06 4472.81,2333.06 697.24,2335.68 717.24,2335.68 737.24,2335.68 541.49,2345.3 541.49,2365.3 1930.1,2378.7 1989.16,2378.7 879.64,2390.63 2584.19,2390.64 2604.19,2390.64 541.65,2396.3 2584.19,2410.64 2604.19,2410.64 1609.88,2415 1629.88,2415 1649.88,2415 1679.88,2415 1699.88,2415 1719.88,2415 1939.53,2429.53 1062.3,2463.32 1217.89,2468.07 1237.89,2468.07 1257.89,2468.07 359,2468.99 1062.14,2494.32 1062.14,2514.32 1868.73,2531.89 1062.14,2534.32 359,2536.99 697.24,2544.62 737.24,2544.62 766.56,2544.62 786.56,2544.62 806.56,2544.62 845.3,2544.62 865.3,2544.62 885.3,2544.62 1939.53,2547.64 1688.49,2549.57 2463.55,2565.2 2483.55,2565.2 359,2570.99 2463.55,2585.2 2483.55,2585.2 435.83,2601.61 671.26,2601.61 2463.55,2605.2 2483.55,2605.2 2176.18,2611.99 2196.18,2611.99 2216.18,2611.99 449.55,2615.33 657.54,2615.33 2463.55,2625.2 2483.55,2625.2 494.72,2631.37 514.72,2631.37 534.72,2631.37 574.72,2631.37 594.72,2631.37 614.72,2631.37 2176.18,2631.99 2196.18,2631.99 2216.18,2631.99 437.98,2637.47 2668.19,2682.61 2688.19,2682.61
  other v2: 3126.18,56.72 3156.18,56.72 3219.34,56.72 3249.34,56.72 3126.18,88.72 3156.18,88.72 3219.34,88.72 3249.34,88.72 3126.18,120.72 3156.18,120.72 3219.34,120.72 3249.34,120.72 3126.18,152.72 3156.18,152.72 3219.34,152.72 3249.34,152.72 3126.18,216.72 3156.18,216.72 3219.34,216.72 3249.34,216.72 3156.18,248.72 3219.34,248.72 3249.34,248.72 3126.18,344.72 3156.18,344.72 3240.02,344.72 3270.02,344.72 3126.18,376.72 3156.18,376.72 3240.02,376.72 3270.02,376.72 3126.18,408.72 3156.18,408.72 3240.02,408.72 3270.02,408.72 3126.18,440.72 3156.18,440.72 3240.02,440.72 3270.02,440.72 3126.18,472.72 3156.18,472.72 3240.02,472.72 3270.02,472.72 3126.18,536.72 3156.18,536.72 3240.02,536.72 3270.02,536.72 3126.18,600.72 3156.18,600.72 3240.02,600.72 3270.02,600.72 3126.18,632.72 3156.18,632.72 3240.02,632.72 3270.02,632.72 3156.18,664.72 3240.02,664.72 3126.18,696.72 3270.02,696.72 3126.18,728.72 3156.18,728.72 3240.02,728.72 3270.02,728.72 3126.18,760.72 3156.18,760.72 3240.02,760.72 3270.02,760.72 3098.72,785.77 3296.49,785.77 3137.56,789.35 3257.65,789.35 3076.09,808.39 3319.12,808.39 3279.28,810.63 3114.93,811.98 3198,817.02 3053.46,831.02 3341.74,831.02 3092.3,832.61 3302.9,832.61 3177.92,835.77 3217.29,835.77 3177.92,1001.41 3217.29,1001.41 3058.99,1004.93 3090.99,1004.93 3304.21,1004.93 3336.21,1004.93 3198,1020.16 3113.62,1027.56 3281.58,1027.56 3058.99,1710.65 3090.99,1710.65 3304.21,1710.65 3336.21,1710.65 3177.92,1714.16 3217.29,1714.16 3197.21,1898.56 3280.28,1903.6 3116,1905 3076.09,1907.18 3319.12,1907.18 3137.56,1926.22 3257.65,1926.22 3098.71,1929.81 3296.49,1929.81 3125.18,1986.85 3155.18,1986.85 3239.02,1986.85 3269.02,1986.85 3125.18,2050.85 3155.18,2050.85 3239.02,2050.85 3269.02,2050.85 3125.18,2082.85 3155.18,2082.85 3239.02,2082.85 3269.02,2082.85 3125.18,2114.85 3155.18,2114.85 3239.02,2114.85 3269.02,2114.85 3125.18,2146.85 3155.18,2146.85 3239.02,2146.85 3269.02,2146.85 3125.18,2178.85 3155.18,2178.85 3239.02,2178.85 3269.02,2178.85 3125.18,2210.85 3155.18,2210.85 3239.02,2210.85 3269.02,2210.85 3125.18,2242.85 3155.18,2242.85 3239.02,2242.85 3269.02,2242.85 3125.18,2274.85 3155.18,2274.85 3239.02,2274.85 3269.02,2274.85 3125.18,2306.85 3155.18,2306.85 3239.02,2306.85 3269.02,2306.85 3125.18,2338.85 3155.18,2338.85 3239.02,2338.85 3269.02,2338.85 3125.18,2370.85 3155.18,2370.85 3239.02,2370.85 3269.02,2370.85 3145.87,2466.85 3175.87,2466.85 3239.02,2466.85 3269.02,2466.85 3145.87,2498.85 3175.87,2498.85 3239.02,2498.85 3269.02,2498.85 3145.87,2530.85 3175.87,2530.85 3239.02,2530.85 3269.02,2530.85 3145.87,2562.85 3175.87,2562.85 3239.02,2562.85 3269.02,2562.85 3145.87,2594.85 3175.87,2594.85 3239.02,2594.85 3269.02,2594.85 3145.87,2626.85 3175.87,2626.85 3239.02,2626.85 3269.02,2626.85 3145.87,2658.85 3175.87,2658.85 3239.02,2658.85 3269.02,2658.85 3145.87,2690.85 3175.87,2690.85 3239.02,2690.85 3269.02,2690.85
  other v3: 512.2,2475.96 537.8,2475.96 512.2,2501.55 537.8,2501.55 512.2,2533.05 537.8,2533.05 572.24,2533.05 612.6,2533.05 512.2,2558.64 537.8,2558.64 572.24,2558.64 612.6,2558.64
  other v4: 3197.6,296.56 3197.6,2419.02 2301.04,2431.05 2287.27,2460.58 2314.82,2460.58 2301.04,2490.1
HSPC-PRSNT-M2C-L: J1.Z1 R234.2
  other v1: 4422.81,2333.06
LMK_C\S\: PP31.1 U14.18 U31.10 | length 3035.7
  Top Layer w5: U31.10@931.94,1655.92 v1(951.94,1655.92) ; U14.18@2732.48,1786.92 2732.48,1842.02 2728.14,1846.36 2728.14,1874.75 2754.44,1901.05 2828.2,1901.05 PP31.1@2873.51,1946.36
  L7 Ctrl Signal 1 w5: v1(951.94,1655.92) 998.7,1655.92 1059.6,1716.81 1416.71,1716.81 1673.36,1973.47 2104.98,1973.47 2174.59,2043.08 2174.59,2276.79 2344.31,2446.51 2642.9,2446.51 2704.78,2384.63 2704.78,2115.09 PP31.1@2873.51,1946.36
LMK_CLKIN0_n: C66.2 U14.38 | length 64.9
  Top Layer w10: C66.2@2374.73,1642.91 2394.17,1642.91 2414.17,1662.91 U14.38@2431.3,1662.91
LMK_CLKIN0_p: C64.2 C65.2 U14.37 | length 63.2
  Top Layer w10: C64.2@2374.73,1666.59 2375.21,1667.07 2388.86,1667.07 2404.38,1682.59 U14.37@2431.3,1682.59
LMK_CLKIN1_n: C89.2 U14.35 | length 63.2
  Top Layer w10: C89.2@2374.73,1737.96 2375.21,1737.48 2388.86,1737.48 2404.38,1721.96 U14.35@2431.3,1721.96
LMK_CLKIN1_p: C83.2 C88.2 U14.34 | length 64.9
  Top Layer w10: C83.2@2374.73,1761.65 2394.17,1761.65 2414.17,1741.65 U14.34@2431.3,1741.65
LMK_SCLK: PP25.1 U14.19 U31.2 | length 2463.9
  Top Layer w5: U14.19@2712.8,1786.92 2712.8,1879.54 2766.62,1933.36 2766.62,1939.47 PP25.1@2773.51,1946.36
  Top Layer w8: v1(838.95,1671.67) U31.2@868.95,1671.67
  L7 Ctrl Signal 1 w5: v1(838.95,1671.67) 815.38,1648.1 815.38,1628.95 872.28,1572.05 924.64,1572.05 946.15,1550.54 958.99,1550.54 987,1578.55 1098.81,1578.55 1160.43,1640.17 1473.72,1640.17 1747.52,1913.97 2174.59,1913.97 2223.46,1962.84 2655.16,1962.84 2706.2,1911.8 2738.95,1911.8 PP25.1@2773.51,1946.36
LMK_SDI: PP27.1 U14.20 U31.5 | length 2767.4
  Top Layer w5: v1(876.82,1596.55) U31.5@876.82,1616.55 ; U14.20@2693.11,1786.92 2693.11,1915.96 PP27.1@2723.51,1946.36
  L7 Ctrl Signal 1 w5: v1@877.09,1596.28 892.32,1581.05 914.74,1581.05 921.24,1587.55 1094.09,1587.55 1170.7,1664.16 1484.99,1664.16 1754.68,1933.85 2156.63,1933.85 2220.24,1997.46 2220.24,2241.91 2299.44,2321.1 2549.75,2321.1 2666.46,2204.39 2666.46,2003.41 PP27.1@2723.51,1946.36
LMK_SDO: PP29.1 U14.58 U31.7 | length 3395
  Top Layer w5: v1(908.32,1596.55) U31.7@908.32,1616.55
  L7 Ctrl Signal 1 w5: v1(908.32,1596.55) 1087.43,1596.55 1166.97,1676.1 1481.8,1676.1 1757.56,1951.85 2110,1951.85 2196.18,2038.03 2196.18,2252.58 2343,2399.4 2545.73,2399.4 2604.19,2340.94 2662.14,2340.94 2686.94,2316.15 2686.94,2082.93 PP29.1@2823.51,1946.36 2823.51,1877.34 2865.4,1835.45 2865.4,1564.04 2834.66,1533.3 2807.02,1533.3 2726,1452.28 v1(2634.06,1452.28)
LMX_C\S\: U26.3 U28.10 | length 373.4
  Top Layer w5: v1(948.95,1325.92) U26.3@988.95,1325.92 ; U28.10@991.94,1490.92 v1(1031.94,1490.92)
  L7 Ctrl Signal 1 w5: v1(948.95,1325.92) 948.95,1295.85 958.26,1286.55 984.38,1286.55 991.82,1293.99 991.82,1417.38 999.57,1425.13 999.57,1458.54 v1(1031.94,1490.92)
LMX_CLKOUT0_n: C140.2 U25.15 | length 633.7
  Top Layer w6.5: U25.15@2377.76,1270.15 2800.59,1270.15 cw(c2800.59,1159.91) 2878.55,1237.86 2887.83,1228.58 ccw(c2938.91,1279.65) 2938.91,1207.42 2973.12,1207.42 ccw(c2973.12,1212.06) 2977.76,1212.06
  Top Layer w10: 2977.76,1212.06 C140.2@2977.76,1224.99
LMX_CLKOUT0_p: C138.2 U25.14 | length 635.1
  Top Layer w6.5: U25.14@2377.76,1250.46 2384.65,1250.46 2389.24,1255.06 2800.59,1255.06 cw(c2800.59,1159.91) 2867.88,1227.19 2877.16,1217.91 ccw(c2938.91,1279.65) 2938.91,1192.33 2973.99,1192.33 cw(c2973.99,1188.56) 2977.76,1188.56
  Top Layer w10: C138.2@2977.76,1175.62 2977.76,1188.56
LMX_DAC_SYSREF_n: C73.1 C144.1 | length 710.9
  Top Layer w10: C144.1@2506.85,1213.14 2526.85,1213.14 v1(2526.85,1213.64)
  Bottom Layer w6.5: v1(2526.85,1213.64) ccw(c2534.45,1213.64) 2534.45,1206.05 2631.61,1206.05 ccw(c2631.61,1306.05) 2702.32,1235.34 2787.76,1320.78 ccw(c2775.79,1332.75) 2792.72,1332.75 2792.72,1369.74 cw(c2855.33,1369.74) 2855.33,1432.35 2855.44,1432.35 ccw(c2855.44,1475.48) 2898.57,1475.48 cw(c2943.61,1475.48) 2943.61,1520.52 2992.88,1520.52 ccw(c2992.88,1527.45) 2999.81,1527.45
  Bottom Layer w10: 2999.81,1527.45 v1(2999.81,1562)
LMX_DAC_SYSREF_p: C74.1 C143.1 | length 710.9
  Top Layer w10: C143.1@2506.85,1188.46 2526.85,1188.46 v1(2526.85,1187.96)
  Bottom Layer w6.5: v1(2526.85,1187.96) cw(c2534.45,1187.96) 2534.45,1195.55 2631.73,1195.55 ccw(c2631.73,1305.75) 2709.66,1227.83 2795.24,1313.41 ccw(c2775.97,1332.68) 2803.22,1332.68 2803.22,1369.63 cw(c2855.44,1369.63) 2855.44,1421.85 ccw(c2855.44,1475.48) 2909.07,1475.48 cw(c2943.61,1475.48) 2943.61,1510.02 2992.88,1510.02 cw(c2992.88,1503.09) 2999.81,1503.09
  Bottom Layer w10: v1(2999.81,1468.54) 2999.81,1503.09
LMX_LOGIC_CLK_n: C155.1 R70.1 | length 284.2
  Top Layer w6.5: C155.1@2235.81,1511.21 cw(c2235.81,1517.8) 2229.22,1517.8 2229.22,1723.63 cw(c2250,1723.63) 2250,1744.41 2275.29,1744.41 cw(c2275.29,1737.96) R70.1@2281.74,1737.96
LMX_LOGIC_CLK_p: C153.1 R68.1 | length 300.4
  Top Layer w6.5: C153.1@2212.62,1511.21 ccw(c2212.62,1517.8) 2219.22,1517.8 2219.22,1723.63 cw(c2250,1723.63) 2250,1754.41 2274.5,1754.41 ccw(c2274.5,1761.65) R68.1@2281.74,1761.65
LMX_LOGIC_SYSREF_n: C157.1 R65.1 | length 206.6
  Top Layer w6.5: R65.1@2281.64,1643.12 2281.64,1643.71 ccw(c2275,1643.71) 2275,1650.35 2265.35,1650.35 ccw(c2265.35,1640) 2255,1640 2255,1560.19 ccw(c2264.21,1560.19) 2264.21,1550.98 2280.05,1550.98 cw(c2280.05,1523.08) 2307.96,1523.08 2307.96,1517.55 2308.21,1517.55 ccw(c2314.55,1517.55) C157.1@2314.55,1511.21
LMX_LOGIC_SYSREF_p: C156.1 R63.1 | length 222.3
  Top Layer w6.5: R63.1@2281.64,1667.59 2281.64,1666.99 cw(c2275,1666.99) 2275,1660.35 2265.35,1660.35 ccw(c2265.35,1640) 2245,1640 2245,1560.19 ccw(c2264.21,1560.19) 2264.21,1540.98 2280.05,1540.98 cw(c2280.05,1523.08) 2297.96,1523.08 2297.96,1517.55 2297.71,1517.55 cw(c2291.36,1517.55) C156.1@2291.36,1511.21
LMX_LOGICCLK_n: C155.2 R130.2 R139.1 U25.27 | length 129.8
  Top Layer w6.5: U25.27@2229.47,1398.76 ccw(c2234.06,1398.76) U25.27@2234.06,1394.17 cw(c2234.06,1399.01) 2229.22,1399.01 2229.22,1420.32 cw(c2234.06,1420.32) 2234.06,1425.17 cw(c2234.06,1430.01) 2229.22,1430.01 2229.22,1443.32 cw(c2234.06,1443.32) 2234.06,1448.17 cw(c2234.06,1453.01) 2229.22,1453.01 2229.22,1482.57 cw(c2235.81,1482.57) C155.2@2235.81,1489.17 ccw(c2235.81,1482.82) 2229.47,1482.82
LMX_LOGICCLK_p: C153.2 R129.2 R138.1 U25.28 | length 129.8
  Top Layer w6.5: U25.28@2218.97,1398.76 cw(c2214.37,1398.76) U25.28@2214.37,1394.17 ccw(c2214.37,1399.01) 2219.22,1399.01 2219.22,1420.32 ccw(c2214.37,1420.32) 2214.37,1425.17 ccw(c2214.37,1430.01) 2219.22,1430.01 2219.22,1443.32 ccw(c2214.37,1443.32) 2214.37,1448.17 ccw(c2214.37,1453.01) 2219.22,1453.01 2219.22,1482.57 ccw(c2212.62,1482.57) C153.2@2212.62,1489.17 cw(c2212.62,1482.82) 2218.97,1482.82
LMX_LOGICSYSREFOUT0_n: C157.2 R132.2 R141.1 U25.23 | length 137
  Top Layer w6.5: 2308.21,1482.82 cw(c2314.55,1482.82) C157.2@2314.55,1489.17 ccw(c2314.55,1482.57) 2307.96,1482.57 2307.96,1453.01 ccw(c2312.8,1453.01) 2312.8,1448.17 ccw(c2312.8,1443.32) 2307.96,1443.32 2307.96,1430.01 ccw(c2312.8,1430.01) 2312.8,1425.17 ccw(c2312.8,1420.32) 2307.96,1420.32 2307.96,1399.01 ccw(c2312.8,1399.01) U25.23@2312.8,1394.17 ; U25.23@2312.8,1394.17 cw(c2312.8,1398.76) 2308.21,1398.76 ccw(c2312.8,1398.76) U25.23@2312.8,1394.17
LMX_LOGICSYSREFOUT0_p: C156.2 R131.2 R140.1 U25.24 | length 137
  Top Layer w6.5: C156.2@2291.36,1489.17 cw(c2291.36,1482.82) 2297.71,1482.82 ; C156.2@2291.36,1489.17 cw(c2291.36,1482.57) 2297.96,1482.57 2297.96,1453.01 cw(c2293.11,1453.01) 2293.11,1448.17 cw(c2293.11,1443.32) 2297.96,1443.32 2297.96,1430.01 cw(c2293.11,1430.01) 2293.11,1425.17 cw(c2293.11,1420.32) 2297.96,1420.32 2297.96,1399.01 cw(c2293.11,1399.01) U25.24@2293.11,1394.17 ; U25.24@2293.11,1394.17 ccw(c2293.11,1398.76) 2297.71,1398.76 cw(c2293.11,1398.76) U25.24@2293.11,1394.17
LMX_SCLK: U26.1 U28.2 | length 248
  Top Layer w5: U28.2@928.95,1506.67 902.78,1506.67 893.45,1497.34 893.45,1495.42 888.95,1490.92 888.95,1459.83 907.44,1441.33 907.44,1398.92 948.95,1357.41 U26.1@990.92,1357.41
LMX_SDI: U26.2 U28.5 | length 173.1
  Top Layer w5: v1(928.95,1341.67) U26.2@988.95,1341.67
  Top Layer w8: v1(936.82,1431.55) U28.5@936.82,1451.55
  L10 Ctrl Signal 2 w5: v1(928.95,1341.67) 928.95,1365.92 936.82,1373.79 v1(936.82,1431.55)
LMX_SDO: U26.4 U28.7 | length 169.9
  Top Layer w5: v1(958.32,1411.55) 968.32,1421.55 U28.7@968.32,1451.55 ; v1(968.95,1310.17) U26.4@988.95,1310.17
  L7 Ctrl Signal 1 w5: v1(958.32,1411.55) 968.95,1400.92 v1(968.95,1310.17)
LMX_SYSREFOUT0_n: R121.1 U25.12 | length 35.8
  Top Layer w10: U25.12@2377.76,1211.09 2409.97,1211.09 2411.97,1213.09 R121.1@2412.76,1213.09
LMX_SYSREFOUT0_p: R119.1 U25.11 | length 35.8
  Top Layer w10: U25.11@2377.76,1191.41 2409.97,1191.41 2411.97,1189.41 R119.1@2412.76,1189.41
NetC1_1: C1.1 D2.2 J2.1 Q1.3 SW1.1 TP4.1
NetC1_2: C1.2 D2.1 J2.2 Q1.1 Q1.2 Q1.5 Q1.6 Q1.8
NetC2_2: C2.2 C3.2 D1.1 F1.1 R1.2 U2.6 U2.7 U2.8 U3.D3 | length 61.2
  Bottom Layer w8: R1.2@1040.24,312.22 1045.63,312.22 1059.59,326.18 U3.D3@1059.59,362.22
NetC5_2: C5.2 R2.1 R4.2 U2.2
NetC6_2: C6.2 U2.1
NetC11_2: C11.2 C21.2 C22.2 FC1.3 R16.2 R17.2 U6.15 U6.16 U6.17 | length 123.7
  Bottom Layer w8: v1(1820.34,2291.36) 1858.91,2252.79 v1(1858.91,2183.62)
NetC13_2: C13.2 U6.13 | length 35
  Top Layer w8: C13.2@1859.71,2257.68 U6.13@1894.71,2257.68
NetC14_1: C14.1 U6.3 | length 83.2
  Top Layer w8: U6.3@2024.63,2257.68 2043.52,2257.68 2043.68,2257.52 2071.51,2257.52 2082.24,2246.78 2082.24,2245.19 2094.63,2232.8 C14.1@2094.63,2230.83
NetC17_2: C17.2 C18.2 C19.2 FB1.1 U7.10 U7.11 U7.12 U7.13 U7.14 U7.15 U7.27
NetC23_2: C23.2 U7.21 | length 64.7
  Top Layer w8: C23.2@919.01,2390.63 924.79,2384.84 935.85,2384.84 957.76,2362.93 970.9,2362.93 U7.21@971.82,2362.01
NetC24_2: C24.2 C25.2 FC2.3 R31.2 U8.7 U8.8 | length 123.9
  Bottom Layer w8: v1@1723,2569 1723,2567.35 1727.11,2563.24 1728.76,2563.24 1759,2533 v1(1759,2461)
  other v1: 1722.49,2565.16
NetC27_2: C27.2 U8.6 | length 75.3
  Top Layer w8: C27.2@1688.49,2510.2 1688.49,2508.23 1694.33,2502.39 1696.83,2502.39 1699.02,2500.2 U8.6@1758.49,2500.2
NetC32_1: C32.1 U9.13 | length 41.5
  Top Layer w8: C32.1@965.96,2048.95 966.74,2048.95 969.04,2046.65 969.04,2045.87 980.64,2034.27 U9.13@980.64,2013.95
NetC32_2: C32.2 U9.14 | length 42.1
  Top Layer w8: C32.2@943.91,2048.95 943.91,2040.66 960.04,2024.54 960.04,2014.87 U9.14@960.96,2013.95
NetC38_2: C38.2 U9.6 | length 78.3
  Top Layer w8: C38.2@940.96,1852.43 940.96,1887.1 960.96,1907.1 U9.6@960.96,1922.42
NetC41_2: C41.2 C42.2 C43.2 FB2.1 U11.10 U11.11 U11.12 U11.13 U11.14 U11.15 U11.27
NetC44_2: C44.2 FB2.2 FC3.1 PP3.1 R50.2 | length 563.2
  Bottom Layer w8: v1(95.4,881.98) 171.68,881.98 221.54,931.84 624.35,931.84 633.74,922.45 v1(634.03,922.45)
NetC47_2: C47.2 U11.21 | length 64.7
  Top Layer w8: C47.2@134.77,915.98 140.55,910.2 151.61,910.2 173.52,888.28 186.66,888.28 U11.21@187.58,887.36
NetC51_2: C51.2 R57.2 R59.2 U12.D3 U13.8 U13.9 U13.10 | length 91.2
  Top Layer w8: R57.2@1137.11,1131.85 1150,1118.96 1158.57,1118.96 R57.2@1160.86,1116.67 ; R57.2@1160.86,1116.63 1184.76,1092.73 1196.7,1092.73 U12.D3@1207.58,1081.85
NetC52_2: C52.2 FB3.2 FC4.1 FC5.1 FC6.1 PP4.1
NetC56_2: C56.2 R61.2 U13.7 | length 44
  Top Layer w9: U13.7@962.11,1098.78 996.76,1098.78 1002.11,1093.44 R61.2@1002.11,1091.69
NetC64_1: C64.1 J4.1 R62.2 | length 373.8
  Top Layer w8: v1@2335.48,1692.43 R62.2@2351.78,1692.43
  Top Layer w10: R62.2@2351.78,1692.43 2373.44,1692.43 2374.73,1691.13 C64.1@2374.73,1690.42
  Bottom Layer w8: v1(2020,1720.62) 2171.92,1720.62 cw(c2171.92,1705.31) 2187.23,1705.31 2187.23,1701.38 ccw(c2196.18,1701.38) 2196.18,1692.43 v1@2335.48,1692.43
  other v1: 2335.48,1691.43
NetC65_1: C65.1 R63.2 R64.2 | length 48.5
  Top Layer w10: R63.2@2303.69,1667.59 ccw(c2304.53,1667.59) 2304.53,1666.75 R64.2@2327.69,1666.75 ; R64.2@2328.69,1667.59 C65.1@2352.69,1667.59
NetC66_1: C66.1 R64.1 R65.2 R66.2 | length 49.8
  Top Layer w10: R65.2@2303.69,1643.12 2326.1,1643.12 ccw(c2326.1,1644.7) R64.1@2327.69,1644.7 ; R64.1@2328.69,1642.33 2351.11,1642.33 ccw(c2351.11,1643.91) C66.1@2352.69,1643.91
NetC83_1: C83.1 J5.1 R67.2 | length 372.8
  Top Layer w10: C83.1@2374.73,1783.69 R67.2@2374.73,1806.69 2374.73,1888.6 cw(c2399.54,1888.6) 2381.99,1906.12 2427.72,1951.85 ccw(c2410.79,1968.79) 2434.73,1968.79 J5.1@2434.73,2133.69
NetC88_1: C88.1 R68.2 R69.2 | length 49.9
  Top Layer w10: R68.2@2303.79,1761.65 2327.95,1761.65 cw(c2327.95,1760.8) R69.2@2328.79,1760.8 2351.85,1760.8 ccw(c2351.85,1761.65) C88.1@2352.69,1761.65
NetC89_1: C89.1 R69.1 R70.2 R71.2 | length 49.8
  Top Layer w10: R70.2@2303.79,1737.96 cw(c2304.58,1737.96) 2304.58,1738.76 R69.1@2328.79,1738.76 2351.89,1738.76 cw(c2351.89,1737.96) C89.1@2352.69,1737.96
NetC94_2: C94.2 U14.11 | length 27.1
  Top Layer w10: U14.11@2777.76,1662.91 2795.59,1662.91 2800.59,1657.91 v1(2802.76,1657.91)
NetC95_2: C95.2 U14.12
  other v1: 2777.76,1682.59
NetC99_1: C99.1 U15.10 | length 29.7
  Top Layer w8: C99.1@1187.56,1473.7 cw(c1188.74,1473.7) 1188.74,1474.88 U15.10@1216.56,1474.88
NetC99_2: C99.2 U15.9 | length 29.7
  Top Layer w8: C99.2@1187.56,1495.75 ccw(c1188.74,1495.75) 1188.74,1494.57 U15.9@1216.56,1494.57
NetC100_2: C100.2 FC7.1 R85.2 U15.6
NetC104_2: C104.2 U15.5 | length 52.1
  Top Layer w8: U15.5@1291.37,1514.25 1326.44,1514.25 ccw(c1326.44,1525.08) C104.2@1337.27,1525.08
NetC107_1: C107.1 U17.10 | length 29.7
  Top Layer w8: U17.10@1800.79,1607.74 1828.61,1607.74 ccw(c1828.61,1608.92) C107.1@1829.79,1608.92
NetC107_2: C107.2 U17.9 | length 29.7
  Top Layer w8: U17.9@1800.79,1588.05 1828.61,1588.05 cw(c1828.61,1586.87) C107.2@1829.79,1586.87
NetC108_2: C108.2 FC8.1 R90.2 U17.6
NetC112_2: C112.2 U17.5 | length 52.1
  Top Layer w8: C112.2@1680.08,1557.54 cw(c1690.91,1557.54) 1690.91,1568.37 U17.5@1725.98,1568.37
NetC116_2: C116.2 R96.2 R98.2 U18.D3 U19.8 U19.9 U19.10 | length 91.2
  Top Layer w8: R96.2@1233.61,671.85 1246.5,658.96 1255.1,658.96 1281.33,632.73 1293.2,632.73 U18.D3@1304.08,621.85
NetC117_2: C117.2 FB4.2 FC9.1 PP13.1
NetC121_2: C121.2 R100.2 U19.7 | length 44
  Top Layer w9: U19.7@1058.61,638.78 1093.26,638.78 1098.61,633.44 R100.2@1098.61,631.69
NetC124_2: C124.2 R105.2 R108.2 U20.D3 U21.8 U21.9 U21.10 | length 91.2
  Top Layer w8: R105.2@1233.61,921.85 1246.5,908.96 1255.97,908.96 1282.2,882.73 1293.2,882.73 U20.D3@1304.08,871.85
NetC125_2: C125.2 FB5.2 FC10.1 PP16.1
NetC128_2: C128.2 R110.2 U21.7 | length 44
  Top Layer w9: U21.7@1058.61,888.78 1093.26,888.78 1098.61,883.44 R110.2@1098.61,881.69
NetC130_1: C130.1 R117.1 R118.2
NetC131_1: C131.1 U24.3 | length 474.6
  Top Layer w10: v1(2669.08,1100.59) 2669.08,1131.03 cw(c2692.75,1131.03) C131.1@2692.75,1154.69
  Bottom Layer w10: U24.3@2370.3,923.52 2370.3,940.44 cw(c2428.68,940.44) 2387.4,981.72 cw(c2431.48,937.64) 2431.48,999.98 2569.08,999.98 ccw(c2569.08,1099.98) 2625.71,1017.55 ccw(c2569.08,1099.98) 2669.08,1099.98 v1(2669.08,1100.59)
NetC131_2: C131.2 T1.2 | length 35
  Top Layer w10: C131.2@2714.8,1154.69 T1.2@2749.8,1154.69
NetC134_1: C134.1 R118.1 T1.6 | length 213.7
  Top Layer w10: T1.6@2821.8,1126.69 v1(2840.8,1126.69)
  Bottom Layer w10: v1(2840.8,1126.69) 2889.14,1126.69 ccw(c2889.14,1144.06) 2906.52,1144.06 2906.52,1152.41 cw(c2925.28,1152.41) 2925.28,1171.17 R118.1@2952,1171.17 cw(c2952,1110.31) 2995.03,1153.35 v1(2999.81,1148.58)
NetC135_1: C135.1 R117.2 T1.4 | length 216
  Top Layer w10: T1.4@2821.8,1182.69 v1(2840.8,1182.69)
  Bottom Layer w10: v1(2840.8,1182.69) 2879.14,1182.69 ccw(c2879.14,1200.06) 2896.52,1200.06 2896.52,1210.68 cw(c2915.28,1210.68) 2915.28,1229.44 R117.2@2952,1229.44 ccw(c2952,1290.3) 2995.03,1247.27 v1(2999.81,1252.04)
NetC136_1: C136.1 U24.1 | length 111.6
  Top Layer w10: C136.1@2320.45,787.05 v1(2320.45,805.05)
  Bottom Layer w10: v1(2320.45,805.05) 2320.45,809.57 cw(c2378.06,809.57) 2337.33,850.31 ccw(c2300.49,887.14) 2352.58,887.14 U24.1@2352.58,890.05
NetC136_2: C136.2 C141.2 J7.1 | length 190.5
  Top Layer w10: J7.1@2130,765 C136.2@2320.45,765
